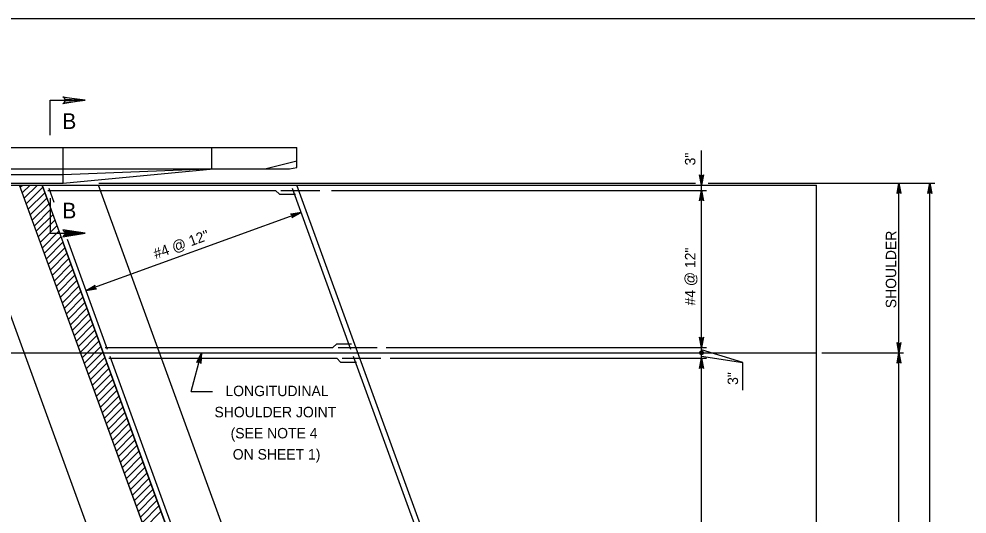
# Model space of a CAD drawing. Extents: x 2084213 to 2099800, y 976677 to 981262.
# Drawn here: x 2094533 to 2095426, y 978110 to 978577 of the extents above; entities that cross this region are included whole.
import ezdxf

# ---------------------------------------------------------------- set-up
doc = ezdxf.new("R2010")
doc.units = 0
doc.layers.add('1', color=7, linetype='Continuous')

msp = doc.modelspace()

# ---------------------------------------------------------------- linework, layer by layer
at = {"layer": '1'}
for p, q in [((2094336.42, 978455.6), (2094676.59, 978455.6)), ((2094340.98, 978455.6), (2094574.37, 978455.6)), ((2094574.37, 978421.85), (2094574.37, 978455.6)), ((2094574.37, 978455.6), (2094794.37, 978455.6)), ((2094714.37, 978435.6), (2094714.37, 978455.6)), ((2094794.37, 978436.72), (2094794.37, 978455.6)), ((2095175.84, 977583.03), (2095175.84, 978452.73)), ((2094764.37, 978435.6), (2094794.37, 978443.1)), ((2094343.7, 978435.6), (2094678.83, 978435.6)), ((2094574.37, 978421.85), (2094716.09, 978435.6)), ((2094574.37, 978429.98), (2094710.12, 978435.6)), ((2094574.37, 978435.6), (2094787.71, 978435.6)), ((2094787.71, 978435.6), (2094794.37, 978436.72)), ((2094345.74, 978429.98), (2094574.37, 978429.98)), ((2094348.7, 978421.85), (2094574.37, 978421.85)), ((2094349.31, 978420.18), (2095284.34, 978420.18)), ((2094769.84, 977623.52), (2094479.88, 978420.18)), ((2094823.05, 977623.52), (2094533.09, 978420.18)), ((2094533.85, 978418.09), (2094535.94, 978420.18)), ((2094535.74, 978412.91), (2094543.01, 978420.18)), ((2094537.62, 978407.73), (2094550.08, 978420.18)), ((2094539.51, 978402.54), (2094555.11, 978418.15)), ((2094560.02, 978404.67), (2094554.37, 978420.18)), ((2094565.71, 978403.66), (2094560.91, 978416.85)), ((2094897.54, 977623.52), (2094607.58, 978420.18)), ((2094607.74, 978421.85), (2095170.33, 978421.85)), ((2094845.47, 978265.18), (2094790.27, 978416.85)), ((2095084.34, 977623.52), (2094794.37, 978420.18)), ((2095182.09, 978421.85), (2095395.99, 978421.85)), ((2095284.34, 977623.52), (2095284.34, 978420.18)), ((2095362.09, 978261.85), (2095362.09, 978421.85)), ((2095391.19, 977621.85), (2095391.19, 978421.85)), ((2094541.4, 978397.36), (2094557, 978412.96)), ((2094543.28, 978392.17), (2094558.89, 978407.78)), ((2094559.74, 978415.18), (2094774.53, 978415.18)), ((2094778.16, 978411.55), (2094774.53, 978415.18)), ((2094778.16, 978411.55), (2094793.25, 978411.55)), ((2094779.34, 978415.18), (2094816.19, 978415.18)), ((2094827.03, 978415.18), (2095180.61, 978415.18)), ((2094545.17, 978386.99), (2094560.77, 978402.59)), ((2094547.06, 978381.81), (2094562.66, 978397.41)), ((2094548.94, 978376.62), (2094564.55, 978392.23)), ((2094798.45, 978394.36), (2094595.92, 978320.65)), ((2094550.83, 978371.44), (2094566.44, 978387.04)), ((2094552.72, 978366.25), (2094568.32, 978381.86)), ((2094554.61, 978361.07), (2094570.21, 978376.67)), ((2094556.49, 978355.88), (2094572.1, 978371.49)), ((2094558.38, 978350.7), (2094573.98, 978366.3)), ((2094830.36, 977661.91), (2094574.19, 978365.74)), ((2094616.11, 978265.18), (2094578.37, 978368.87)), ((2094560.27, 978345.52), (2094575.87, 978361.12)), ((2094562.15, 978340.33), (2094577.76, 978355.94)), ((2094564.04, 978335.15), (2094579.64, 978350.75)), ((2094565.93, 978329.96), (2094581.53, 978345.57)), ((2094567.81, 978324.78), (2094583.42, 978340.38)), ((2094569.7, 978319.6), (2094585.3, 978335.2)), ((2094571.59, 978314.41), (2094587.19, 978330.02)), ((2094573.47, 978309.23), (2094589.08, 978324.83)), ((2094575.36, 978304.04), (2094590.97, 978319.65)), ((2094577.25, 978298.86), (2094592.85, 978314.46)), ((2094579.13, 978293.67), (2094594.74, 978309.28)), ((2094581.02, 978288.49), (2094596.63, 978304.09)), ((2094582.91, 978283.31), (2094598.51, 978298.91)), ((2094584.8, 978278.12), (2094600.4, 978293.73)), ((2094586.68, 978272.94), (2094602.29, 978288.54)), ((2094588.57, 978267.75), (2094604.17, 978283.36)), ((2094590.46, 978262.57), (2094606.06, 978278.17)), ((2094592.34, 978257.39), (2094607.95, 978272.99)), ((2094594.23, 978252.2), (2094609.83, 978267.81)), ((2094613.73, 978266.85), (2094828.52, 978266.85)), ((2094832.15, 978270.48), (2094828.52, 978266.85)), ((2094832.15, 978270.48), (2094846.03, 978270.48)), ((2094833.51, 978266.85), (2094870.18, 978266.85)), ((2094878.78, 978266.85), (2095180.61, 978266.85)), ((2095214.75, 978252.72), (2095175.84, 978264.76)), ((2094406.94, 978261.85), (2095284.34, 978261.85)), ((2094596.12, 978247.02), (2094611.72, 978262.62)), ((2094598, 978241.83), (2094613.61, 978257.44)), ((2094617.37, 978256.85), (2094832.16, 978256.85)), ((2094790.81, 977785.18), (2094618.54, 978258.52)), ((2094694.93, 978225.32), (2094704.65, 978261.85)), ((2094835.79, 978253.22), (2094832.16, 978256.85)), ((2094837.22, 978256.85), (2094873.82, 978256.85)), ((2095020.17, 977785.18), (2094847.89, 978258.52)), ((2094882.47, 978256.85), (2095180.61, 978256.85)), ((2095175.84, 978258.87), (2095214.75, 978252.72)), ((2095289.36, 978261.85), (2095366.19, 978261.85)), ((2095362.09, 977781.85), (2095362.09, 978261.85)), ((2094599.89, 978236.65), (2094615.49, 978252.25)), ((2094601.78, 978231.46), (2094617.38, 978247.07)), ((2094835.79, 978253.22), (2094850.88, 978253.22)), ((2095214.75, 978226.72), (2095214.75, 978252.72)), ((2094603.66, 978226.28), (2094619.27, 978241.88)), ((2094605.55, 978221.1), (2094621.16, 978236.7)), ((2094607.44, 978215.91), (2094623.04, 978231.52)), ((2094609.32, 978210.73), (2094624.93, 978226.33)), ((2094611.21, 978205.54), (2094626.82, 978221.15)), ((2094694.93, 978225.32), (2094714.92, 978225.32)), ((2094613.1, 978200.36), (2094628.7, 978215.96)), ((2094614.99, 978195.17), (2094630.59, 978210.78)), ((2094616.87, 978189.99), (2094632.48, 978205.59)), ((2094618.76, 978184.81), (2094634.36, 978200.41)), ((2094620.65, 978179.62), (2094636.25, 978195.23)), ((2094622.53, 978174.44), (2094638.14, 978190.04)), ((2094624.42, 978169.25), (2094640.02, 978184.86)), ((2094626.31, 978164.07), (2094641.91, 978179.67)), ((2094628.19, 978158.89), (2094643.8, 978174.49)), ((2094630.08, 978153.7), (2094645.68, 978169.31)), ((2094631.97, 978148.52), (2094647.57, 978164.12)), ((2094633.85, 978143.33), (2094649.46, 978158.94)), ((2094635.74, 978138.15), (2094651.35, 978153.75)), ((2094637.63, 978132.96), (2094653.23, 978148.57)), ((2094639.52, 978127.78), (2094655.12, 978143.38)), ((2094641.4, 978122.6), (2094657.01, 978138.2)), ((2094643.29, 978117.41), (2094658.89, 978133.02)), ((2094645.18, 978112.23), (2094660.78, 978127.83)), ((2094647.06, 978107.04), (2094662.67, 978122.65)), ((2094648.95, 978101.86), (2094664.55, 978117.46)), ((2094650.84, 978096.68), (2094666.44, 978112.28))]:
    msp.add_line(p, q, dxfattribs=at)
for points in [[(2096781.61, 976726.46), (2096781.61, 978576.86), (2094202.86, 978576.86), (2094202.86, 976726.46), (2096781.61, 976726.46), (2096781.61, 976812.94), (2096125.44, 976812.94), (2096125.44, 977025.14), (2096781.61, 977025.14), (2096781.61, 977120.16), (2096125.44, 977120.16), (2096125.44, 976726.46), (2096383.97, 976726.46), (2096383.97, 976812.94), (2096383.97, 976726.46), (2096636.6, 976726.46), (2096636.6, 976812.94), (2096636.6, 976772.54), (2096781.61, 976772.54)], [(2094561.87, 978467.08), (2094561.87, 978500.15), (2094594.94, 978500.15)], [(2094574.91, 978502.66), (2094575.66, 978501.22), (2094594.94, 978500.15), (2094574.91, 978502.66), (2094573.89, 978503.54), (2094594.94, 978500.15), (2094575.67, 978499.2), (2094574.98, 978497.76), (2094594.94, 978500.15), (2094573.89, 978496.81), (2094574.98, 978497.76)], [(2095175.84, 978420.18), (2095174, 978429.97), (2095174.26, 978429.59), (2095174.52, 978429.22), (2095174.85, 978429.02), (2095175.18, 978428.83), (2095175.51, 978428.77), (2095175.84, 978428.71), (2095176.16, 978428.77), (2095176.49, 978428.83), (2095176.82, 978429.02), (2095177.15, 978429.22), (2095177.41, 978429.59), (2095177.67, 978429.97), (2095175.84, 978420.18), (2095177.41, 978429.59), (2095177.15, 978429.22), (2095175.84, 978420.18), (2095176.82, 978429.02), (2095176.49, 978428.83), (2095175.84, 978420.18), (2095176.16, 978428.77), (2095175.84, 978428.71), (2095175.84, 978420.18), (2095175.51, 978428.77), (2095175.18, 978428.83), (2095175.84, 978420.18), (2095174.85, 978429.02), (2095174.52, 978429.22), (2095175.84, 978420.18), (2095174.26, 978429.59)], [(2094838.18, 977640.44), (2094844.34, 977623.52), (2094823.05, 977623.52), (2094533.09, 978420.18), (2094554.37, 978420.18), (2094829.85, 977663.3)], [(2095362.09, 978421.85), (2095363.93, 978412.06), (2095363.67, 978412.44), (2095363.41, 978412.82), (2095363.08, 978413.01), (2095362.75, 978413.21), (2095362.42, 978413.26), (2095362.09, 978413.32), (2095361.77, 978413.26), (2095361.44, 978413.21), (2095361.11, 978413.01), (2095360.78, 978412.82), (2095360.52, 978412.44), (2095360.26, 978412.06), (2095362.09, 978421.85), (2095360.52, 978412.44), (2095360.78, 978412.82), (2095362.09, 978421.85), (2095361.11, 978413.01), (2095361.44, 978413.21), (2095362.09, 978421.85), (2095361.77, 978413.26), (2095362.09, 978413.32), (2095362.09, 978421.85), (2095362.42, 978413.26), (2095362.75, 978413.21), (2095362.09, 978421.85), (2095363.08, 978413.01), (2095363.41, 978412.82), (2095362.09, 978421.85), (2095363.67, 978412.44)], [(2095391.19, 978421.85), (2095393.02, 978412.06), (2095392.76, 978412.44), (2095392.5, 978412.82), (2095392.17, 978413.01), (2095391.84, 978413.21), (2095391.52, 978413.26), (2095391.19, 978413.32), (2095390.86, 978413.26), (2095390.53, 978413.21), (2095390.2, 978413.01), (2095389.88, 978412.82), (2095389.61, 978412.44), (2095389.35, 978412.06), (2095391.19, 978421.85), (2095389.61, 978412.44), (2095389.88, 978412.82), (2095391.19, 978421.85), (2095390.2, 978413.01), (2095390.53, 978413.21), (2095391.19, 978421.85), (2095390.86, 978413.26), (2095391.19, 978413.32), (2095391.19, 978421.85), (2095391.52, 978413.26), (2095391.84, 978413.21), (2095391.19, 978421.85), (2095392.17, 978413.01), (2095392.5, 978412.82), (2095391.19, 978421.85), (2095392.76, 978412.44)], [(2094561.87, 978407.73), (2094561.87, 978374.66), (2094594.94, 978374.66)], [(2095175.84, 978415.18), (2095177.67, 978405.4), (2095177.41, 978405.78), (2095177.15, 978406.15), (2095176.82, 978406.35), (2095176.49, 978406.54), (2095176.16, 978406.6), (2095175.84, 978406.65), (2095175.51, 978406.6), (2095175.18, 978406.54), (2095174.85, 978406.35), (2095174.52, 978406.15), (2095174.26, 978405.78), (2095174, 978405.4), (2095175.84, 978415.18), (2095174.26, 978405.78), (2095174.52, 978406.15), (2095175.84, 978415.18), (2095174.85, 978406.35), (2095175.18, 978406.54), (2095175.84, 978415.18), (2095175.51, 978406.6), (2095175.84, 978406.65), (2095175.84, 978415.18), (2095176.16, 978406.6), (2095176.49, 978406.54), (2095175.84, 978415.18), (2095176.82, 978406.35), (2095177.15, 978406.15), (2095175.84, 978415.18), (2095177.41, 978405.78)], [(2094798.45, 978394.36), (2094789.88, 978389.29), (2094790.15, 978389.66), (2094790.41, 978390.04), (2094790.48, 978390.41), (2094790.55, 978390.79), (2094790.49, 978391.12), (2094790.43, 978391.44), (2094790.27, 978391.73), (2094790.1, 978392.02), (2094789.81, 978392.26), (2094789.51, 978392.51), (2094789.07, 978392.62), (2094788.63, 978392.74), (2094798.45, 978394.36), (2094789.07, 978392.62), (2094789.51, 978392.51), (2094798.45, 978394.36), (2094789.81, 978392.26), (2094790.1, 978392.02), (2094798.45, 978394.36), (2094790.27, 978391.73), (2094790.43, 978391.44), (2094798.45, 978394.36), (2094790.49, 978391.12), (2094790.55, 978390.79), (2094798.45, 978394.36), (2094790.48, 978390.41), (2094790.41, 978390.04), (2094798.45, 978394.36), (2094790.15, 978389.66)], [(2094574.91, 978372.15), (2094575.66, 978373.6), (2094594.94, 978374.66), (2094574.91, 978372.15), (2094573.89, 978371.27), (2094594.94, 978374.66), (2094575.67, 978375.62), (2094574.98, 978377.05), (2094594.94, 978374.66), (2094573.89, 978378.01), (2094574.98, 978377.05)], [(2094595.92, 978320.65), (2094604.49, 978325.72), (2094604.22, 978325.34), (2094603.96, 978324.97), (2094603.89, 978324.59), (2094603.82, 978324.22), (2094603.88, 978323.89), (2094603.94, 978323.56), (2094604.1, 978323.28), (2094604.27, 978322.99), (2094604.56, 978322.74), (2094604.86, 978322.5), (2094605.3, 978322.39), (2094605.74, 978322.27), (2094595.92, 978320.65), (2094605.3, 978322.39), (2094604.86, 978322.5), (2094595.92, 978320.65), (2094604.56, 978322.74), (2094604.27, 978322.99), (2094595.92, 978320.65), (2094604.1, 978323.28), (2094603.94, 978323.56), (2094595.92, 978320.65), (2094603.88, 978323.89), (2094603.82, 978324.22), (2094595.92, 978320.65), (2094603.89, 978324.59), (2094603.96, 978324.97), (2094595.92, 978320.65), (2094604.22, 978325.34)], [(2095175.84, 978266.85), (2095174, 978276.64), (2095174.26, 978276.26), (2095174.52, 978275.88), (2095174.85, 978275.69), (2095175.18, 978275.49), (2095175.51, 978275.44), (2095175.84, 978275.38), (2095176.16, 978275.44), (2095176.49, 978275.49), (2095176.82, 978275.69), (2095177.15, 978275.88), (2095177.41, 978276.26), (2095177.67, 978276.64), (2095175.84, 978266.85), (2095177.41, 978276.26), (2095177.15, 978275.88), (2095175.84, 978266.85), (2095176.82, 978275.69), (2095176.49, 978275.49), (2095175.84, 978266.85), (2095176.16, 978275.44), (2095175.84, 978275.38), (2095175.84, 978266.85), (2095175.51, 978275.44), (2095175.18, 978275.49), (2095175.84, 978266.85), (2095174.85, 978275.69), (2095174.52, 978275.88), (2095175.84, 978266.85), (2095174.26, 978276.26)], [(2095362.09, 978261.85), (2095360.26, 978271.64), (2095360.52, 978271.26), (2095360.78, 978270.88), (2095361.11, 978270.69), (2095361.44, 978270.49), (2095361.77, 978270.44), (2095362.09, 978270.38), (2095362.42, 978270.44), (2095362.75, 978270.49), (2095363.08, 978270.69), (2095363.41, 978270.88), (2095363.67, 978271.26), (2095363.93, 978271.64), (2095362.09, 978261.85), (2095363.67, 978271.26), (2095363.41, 978270.88), (2095362.09, 978261.85), (2095363.08, 978270.69), (2095362.75, 978270.49), (2095362.09, 978261.85), (2095362.42, 978270.44), (2095362.09, 978270.38), (2095362.09, 978261.85), (2095361.77, 978270.44), (2095361.44, 978270.49), (2095362.09, 978261.85), (2095361.11, 978270.69), (2095360.78, 978270.88), (2095362.09, 978261.85), (2095360.52, 978271.26)], [(2094704.65, 978261.85), (2094703.91, 978251.92), (2094703.75, 978252.35), (2094703.6, 978252.78), (2094703.33, 978253.06), (2094703.06, 978253.33), (2094702.76, 978253.47), (2094702.46, 978253.61), (2094702.13, 978253.64), (2094701.8, 978253.67), (2094701.43, 978253.56), (2094701.06, 978253.46), (2094700.71, 978253.16), (2094700.36, 978252.87), (2094704.65, 978261.85), (2094700.71, 978253.16), (2094701.06, 978253.46), (2094704.65, 978261.85), (2094701.43, 978253.56), (2094701.8, 978253.67), (2094704.65, 978261.85), (2094702.13, 978253.64), (2094702.46, 978253.61), (2094704.65, 978261.85), (2094702.76, 978253.47), (2094703.06, 978253.33), (2094704.65, 978261.85), (2094703.33, 978253.06), (2094703.6, 978252.78), (2094704.65, 978261.85), (2094703.75, 978252.35)], [(2095175.84, 978256.85), (2095177.67, 978247.06), (2095177.41, 978247.44), (2095177.15, 978247.82), (2095176.82, 978248.01), (2095176.49, 978248.21), (2095176.16, 978248.26), (2095175.84, 978248.32), (2095175.51, 978248.26), (2095175.18, 978248.21), (2095174.85, 978248.01), (2095174.52, 978247.82), (2095174.26, 978247.44), (2095174, 978247.06), (2095175.84, 978256.85), (2095174.26, 978247.44), (2095174.52, 978247.82), (2095175.84, 978256.85), (2095174.85, 978248.01), (2095175.18, 978248.21), (2095175.84, 978256.85), (2095175.51, 978248.26), (2095175.84, 978248.32), (2095175.84, 978256.85), (2095176.16, 978248.26), (2095176.49, 978248.21), (2095175.84, 978256.85), (2095176.82, 978248.01), (2095177.15, 978247.82), (2095175.84, 978256.85), (2095177.41, 978247.44)], [(2095362.09, 978261.85), (2095363.93, 978252.06), (2095363.67, 978252.44), (2095363.41, 978252.82), (2095363.08, 978253.01), (2095362.75, 978253.21), (2095362.42, 978253.26), (2095362.09, 978253.32), (2095361.77, 978253.26), (2095361.44, 978253.21), (2095361.11, 978253.01), (2095360.78, 978252.82), (2095360.52, 978252.44), (2095360.26, 978252.06), (2095362.09, 978261.85), (2095360.52, 978252.44), (2095360.78, 978252.82), (2095362.09, 978261.85), (2095361.11, 978253.01), (2095361.44, 978253.21), (2095362.09, 978261.85), (2095361.77, 978253.26), (2095362.09, 978253.32), (2095362.09, 978261.85), (2095362.42, 978253.26), (2095362.75, 978253.21), (2095362.09, 978261.85), (2095363.08, 978253.01), (2095363.41, 978252.82), (2095362.09, 978261.85), (2095363.67, 978252.44)]]:
    msp.add_lwpolyline(points, dxfattribs=at)
for radius in [1.75, 0.875]:
    msp.add_circle((2095175.84, 978261.85), radius, dxfattribs=at)

# ---------------------------------------------------------------- texts
for s, height, p in [('B', 14.76, (2094573.48, 978473.07)), ('B', 14.76, (2094573.48, 978388.74)), ('LONGITUDINAL', 9.8425, (2094727.15, 978221.07)), ('SHOULDER JOINT', 9.8425, (2094716.85, 978201.14)), ('(SEE NOTE 4', 9.8425, (2094732.07, 978181.22)), ('ON SHEET 1)', 9.8425, (2094734.09, 978161.3))]:
    msp.add_text(s, height=height, dxfattribs=at).set_placement(p)
for s, rotation, p in [('3"', 90, (2095170.17, 978438.71)), ('#4 @ 12"', 20, (2094661.49, 978350.27)), ('SHOULDER', 90, (2095359.48, 978304.02)), ('#4 @ 12"', 90, (2095170.17, 978306.56)), ('3"', 90, (2095210.4, 978231.68))]:
    msp.add_text(s, height=9.843, rotation=rotation, dxfattribs=at).set_placement(p)

doc.saveas('drawing.dxf')
